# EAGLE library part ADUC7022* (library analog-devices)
Precision Analog Microcontroller 12-bit Analog I/O, ARM7TDMI® MCU ADuC7022 Source: Source: http://www.analog.com/UploadedFiles/Data_Sheets/288945048AD7C7019_20_1_2_4_5_6_7_0.pdf
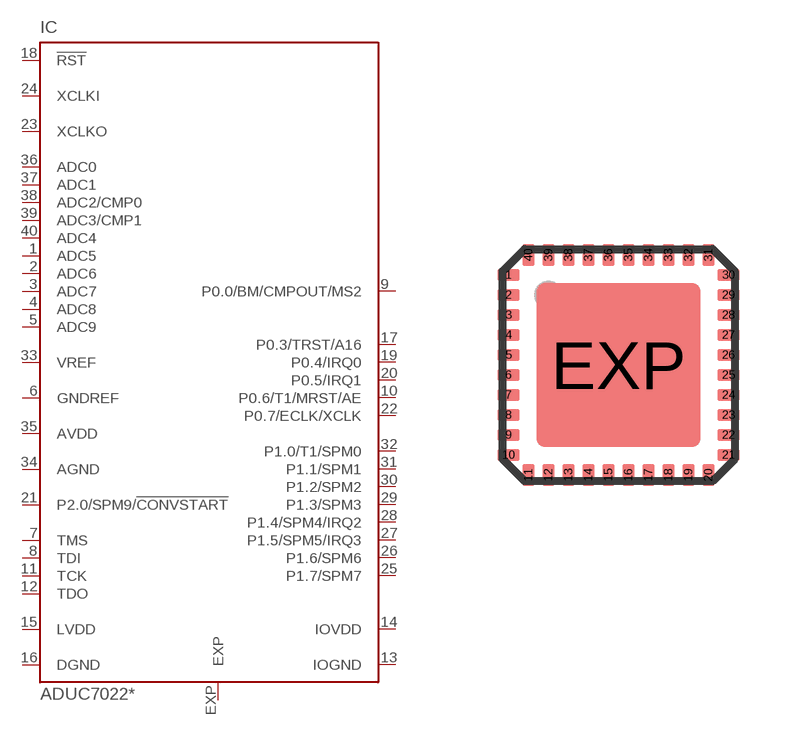
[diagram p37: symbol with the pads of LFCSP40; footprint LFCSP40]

Designator prefix IC

## ADUC7022BCPZ32 (MPN: ADUC7022BCPZ32; OC_FARNELL: 1162638; OC_NEWARK: 19M0739), ADUC7022BCPZ32-RL (OC_FARNELL: unknown; OC_NEWARK: unknown), ADUC7022BCPZ32-RL7 (OC_FARNELL: unknown; OC_NEWARK: unknown), ADUC7022BCPZ62 (MPN: ADUC7022BCPZ62; OC_FARNELL: 1162637; OC_NEWARK: 19M0740), ADUC7022BCPZ62-RL (OC_FARNELL: unknown; OC_NEWARK: unknown), ADUC7022BCPZ62-RL7 (OC_FARNELL: unknown; OC_NEWARK: unknown)  [LFCSP40]
1  ADC5  in
2  ADC6  in
3  ADC7  in
4  ADC8  in
5  ADC9  in
6  GNDREF  in
7  TMS  in
8  TDI  in
9  P0.0/BM/CMPOUT/MS2
10  P0.6/T1/MRST/AE
11  TCK  in
12  TDO  out
13  IOGND  pwr
14  IOVDD  pwr
15  LVDD  out
16  DGND  pwr
17  P0.3/TRST/A16
18  !RST  in
19  P0.4/IRQ0
20  P0.5/IRQ1
21  P2.0/SPM9/!CONVSTART
22  P0.7/ECLK/XCLK
23  XCLKO  out
24  XCLKI  in
25  P1.7/SPM7
26  P1.6/SPM6
27  P1.5/SPM5/IRQ3
28  P1.4/SPM4/IRQ2
29  P1.3/SPM3
30  P1.2/SPM2
31  P1.1/SPM1
32  P1.0/T1/SPM0
33  VREF  pas
34  AGND  pwr
35  AVDD  pwr
36  ADC0  in
37  ADC1  in
38  ADC2/CMP0  in
39  ADC3/CMP1  in
40  ADC4  in
EXP  EXP  pas

## Footprint LFCSP40 (pad centres in mm)
40-Lead Frame Chip Scale Package [LFCSP_VQ] 6 mm x 6 mm Body, Very Thin Quad (CP-40) COMPLIANT TO JEDEC STANDARDS MO-220-VJJD-2 Source: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
smd 0.55 x 0.3: 1 -2.75,2.25; 2 -2.75,1.75; 3 -2.75,1.25; 4 -2.75,0.75; 5 -2.75,0.25; 6 -2.75,-0.25; 7 -2.75,-0.75; 8 -2.75,-1.25; 9 -2.75,-1.75; 10 -2.75,-2.25; 21 2.75,-2.25; 22 2.75,-1.75; 23 2.75,-1.25; 24 2.75,-0.75; 25 2.75,-0.25; 26 2.75,0.25; 27 2.75,0.75; 28 2.75,1.25; 29 2.75,1.75; 30 2.75,2.25
smd 0.3 x 0.55: 11 -2.25,-2.75; 12 -1.75,-2.75; 13 -1.25,-2.75; 14 -0.75,-2.75; 15 -0.25,-2.75; 16 0.25,-2.75; 17 0.75,-2.75; 18 1.25,-2.75; 19 1.75,-2.75; 20 2.25,-2.75; 31 2.25,2.75; 32 1.75,2.75; 33 1.25,2.75; 34 0.75,2.75; 35 0.25,2.75; 36 -0.25,2.75; 37 -0.75,2.75; 38 -1.25,2.75; 39 -1.75,2.75; 40 -2.25,2.75
smd 4.1 x 4.1: EXP 0,0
